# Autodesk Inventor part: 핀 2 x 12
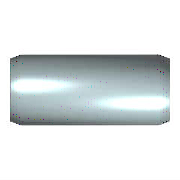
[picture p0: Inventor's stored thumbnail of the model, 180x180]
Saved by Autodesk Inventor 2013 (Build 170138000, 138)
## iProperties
IsCustomPart: 1
Created: 2012-02
Part Number: 핀 2 x 12
Material: 강철, 연강
Description: 평행 핀
Document SubType Name: Modeling
Standard: KS B 1320
Designer: mduedu
Standards Organization: KS
Language: ko-KR
Size Designation: B 2 x  12
Categories: <MemberInstance><Categories><Category DisplayName="조임쇠" InternalName="e4da775c-781d-43d5-af7c-5136215cf5a6" Mnemonic="FSTN"><Category DisplayName="핀" InternalNa
Density: 1 g/cm^3
Author: mduedu
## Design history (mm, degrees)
sketch "스케치"
  geometry: C1 r 1 at (0, 0); 1 further point
  constraints: 1 centre point, 1 coincident
  dimensions: "d1" = 2 diameter of C1 (= NND)
extrude "본체" new body sketch "스케치" distance "d2" = 12 (= NLG); taper "d3" = 0 deg
chamfer "스케치2" distance "d8" = 0.35 (= PHH); stored, may be unused: angle "d9" = 15 deg (= FAWI), second distance "d12" = 0.35 (= PHH)
node "작업 평면1"
body "Solid1"
chamfer "모따기1" distance "d4" = 0.35 (= PHH); stored, may be unused: angle "d5" = 15 deg (= FAWI), second distance "d11" = 0.35 (= PHH)
other parameters: "NND" = 2 [user parameter; used in 1 equation term], "NLG" = 12 [user parameter; used in 1 equation term], "PHH" = 0.35 [user parameter; used in 4 equation terms], "FAWI" = 15 deg [user parameter; used in 2 equation terms], "d13" = 0, "d15" = 0, "d16" = 0, "KAH" = 0.25 [user parameter]
